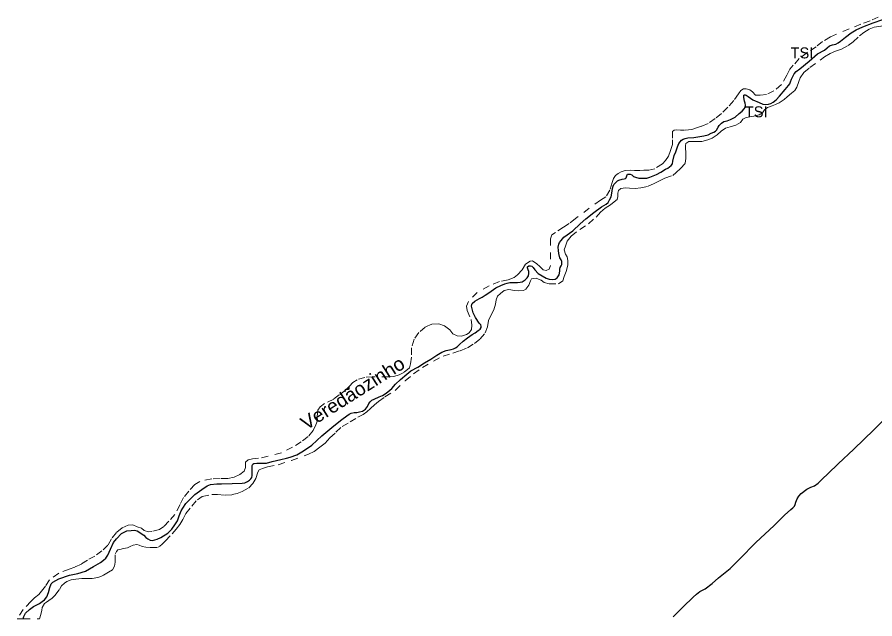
# Model space of a CAD drawing. Extents: x 391.8 to 446, y 8452 to 8507.5.
# Drawn here: x 414.05 to 426.58, y 8452.11 to 8460.91 of the extents above; entities that cross this region are included whole.
import ezdxf
from ezdxf.enums import TextEntityAlignment as Align

# ---------------------------------------------------------------- set-up
doc = ezdxf.new("R2010")
doc.units = 0
doc.header["$LTSCALE"] = 0.064
doc.linetypes.add('SHORT_DASHED', pattern=[2.7, 1.5, -1.2])
for name, color, linetype, lineweight in [('21', 7, 'SHORT_DASHED', 13), ('62', 7, 'SHORT_DASHED', 13), ('7', 7, 'Continuous', 25)]:
    doc.layers.add(name, color=color, linetype=linetype, lineweight=lineweight)
doc.layers.add('61', color=7, linetype='Continuous')

msp = doc.modelspace()

# ---------------------------------------------------------------- linework, layer by layer
at = {"layer": '21'}
for points in [[(426.6341, 8460.9076), (426.5128, 8460.8557), (426.3799, 8460.8037), (426.2065, 8460.7345), (425.935, 8460.6191), (425.8194, 8460.5498), (425.7269, 8460.4748), (425.5998, 8460.394), (425.4785, 8460.3017), (425.3918, 8460.2036), (425.3398, 8460.1459), (425.2994, 8460.0593), (425.2185, 8459.9208), (425.1087, 8459.8285), (424.9989, 8459.7766), (424.9065, 8459.765), (424.8406, 8459.768), (424.7943, 8459.8142), (424.7597, 8459.843), (424.7019, 8459.8603), (424.6672, 8459.8603), (424.6268, 8459.8373), (424.5921, 8459.7853), (424.5228, 8459.6872), (424.4361, 8459.5891), (424.3436, 8459.4968), (424.2512, 8459.4276), (424.1472, 8459.3525), (424.049, 8459.3121), (423.9796, 8459.2891), (423.9103, 8459.266), (423.8005, 8459.2544), (423.7427, 8459.2544), (423.6907, 8459.2602), (423.6503, 8459.2544), (423.6272, 8459.2371), (423.6272, 8459.116), (423.6252, 8459.0441), (423.5963, 8458.9576), (423.5674, 8458.8768), (423.527, 8458.8133), (423.4807, 8458.7614), (423.371, 8458.6921), (423.2843, 8458.669), (423.2092, 8458.669), (423.1514, 8458.6633), (423.0705, 8458.6633), (423.0069, 8458.669), (422.9376, 8458.6633), (422.8798, 8458.646), (422.8336, 8458.6229), (422.7932, 8458.594), (422.7643, 8458.5479), (422.7469, 8458.4902), (422.7123, 8458.3805), (422.6545, 8458.2824), (422.5736, 8458.2305), (422.2096, 8457.965), (422.1171, 8457.89), (422.0362, 8457.8381), (421.9191, 8457.7601), (421.8671, 8457.7255), (421.844, 8457.6678), (421.844, 8457.2754), (421.8267, 8457.2234), (421.7804, 8457.2061), (421.74, 8457.2119)], [(426.3591, 8460.6344), (426.4232, 8460.6833), (426.5023, 8460.7323), (426.5739, 8460.7586), (426.6756, 8460.7737), (426.7849, 8460.8), (426.9205, 8460.8489)], [(421.1665, 8456.9095), (421.2381, 8456.9284), (421.321, 8456.9133), (421.3738, 8456.9058), (421.4491, 8456.9095), (421.4868, 8456.9321), (421.5283, 8456.9886), (421.5509, 8457.0525), (421.5697, 8457.0826), (421.6338, 8457.0939), (421.6715, 8457.0789), (421.7091, 8457.0601), (421.7506, 8457.03), (421.8237, 8457.009), (421.9631, 8457.009), (422.0234, 8457.0541), (422.046, 8457.1181), (422.0724, 8457.1896), (422.0988, 8457.2837), (422.0988, 8457.3477), (422.0912, 8457.4041), (422.0649, 8457.4417), (422.0469, 8457.5074), (422.0658, 8457.5601), (422.0884, 8457.6316), (422.1487, 8457.7068), (422.273, 8457.8047), (422.4011, 8457.8837), (422.5104, 8457.9853), (422.5744, 8458.0568), (422.646, 8458.1133), (422.7214, 8458.1622), (422.7779, 8458.2073), (422.8202, 8458.2428), (422.8315, 8458.2842), (422.8315, 8458.3331), (422.839, 8458.3745), (422.8729, 8458.4008), (422.9408, 8458.4121), (423.0011, 8458.4083), (423.084, 8458.4046), (423.1668, 8458.4121), (423.2724, 8458.4347), (423.3477, 8458.4686), (423.4268, 8458.51), (423.5173, 8458.5513), (423.6303, 8458.5927), (423.6831, 8458.6341), (423.7434, 8458.6943), (423.815, 8458.7734), (423.8239, 8458.8389), (423.8201, 8458.933), (423.8164, 8458.9895), (423.8164, 8459.0309), (423.8239, 8459.061), (423.8654, 8459.0873), (423.9106, 8459.0911), (423.952, 8459.0911), (424.0538, 8459.0873), (424.1442, 8459.1137), (424.2082, 8459.14), (424.2798, 8459.1852), (424.3364, 8459.2416), (424.4004, 8459.2868), (424.472, 8459.3056), (424.5549, 8459.3282), (424.619, 8459.3658), (424.6566, 8459.4147), (424.6943, 8459.4335), (424.7509, 8459.4523), (424.8526, 8459.4674), (424.894, 8459.4787), (424.943, 8459.5088), (424.9732, 8459.554), (425.0146, 8459.5878), (425.0839, 8459.6125), (425.1329, 8459.6313), (425.1857, 8459.6539), (425.261, 8459.7028), (425.3025, 8459.7442), (425.3665, 8459.7969), (425.4155, 8459.8345), (425.4457, 8459.8834), (425.472, 8459.9662), (425.4947, 8460.0227), (425.5474, 8460.0979), (425.6341, 8460.1732), (425.7826, 8460.2769), (425.8504, 8460.3296), (425.9295, 8460.3785), (426.0087, 8460.4086), (426.0953, 8460.4387), (426.1933, 8460.4914), (426.2649, 8460.5479), (426.3591, 8460.6344)], [(421.48, 8457.2985), (421.4337, 8457.2119), (421.3644, 8457.1427), (421.3124, 8457.1023), (421.2257, 8457.0676), (421.0986, 8457.0446), (420.9484, 8456.9811), (420.7751, 8456.883), (420.6459, 8456.7524), (420.6171, 8456.6832), (420.6286, 8456.6197), (420.6864, 8456.487), (420.6979, 8456.4062), (420.6922, 8456.3427), (420.6575, 8456.2908), (420.6171, 8456.2677), (420.5477, 8456.2446), (420.4842, 8456.2504), (420.4206, 8456.2792), (420.3744, 8456.337), (420.2993, 8456.3947), (420.2126, 8456.4235), (420.1144, 8456.4177), (420.0161, 8456.3773), (419.9237, 8456.2966), (419.8544, 8456.1985), (419.8139, 8456.0715), (419.8139, 8455.9388), (419.8024, 8455.8407), (419.785, 8455.783), (419.7019, 8455.7107), (419.6326, 8455.6761), (419.5575, 8455.653), (419.4824, 8455.6473), (419.2512, 8455.6473), (419.1357, 8455.6415), (419.0201, 8455.6069), (418.9566, 8455.5665), (418.9103, 8455.5145), (418.8468, 8455.4511), (418.7601, 8455.3876), (418.6792, 8455.3241), (418.5463, 8455.2606), (418.4828, 8455.2087), (418.4481, 8455.1625), (418.4423, 8455.1164), (418.4365, 8455.0644), (418.4423, 8455.0125), (418.4192, 8454.949), (418.3788, 8454.8625), (418.3036, 8454.7759), (418.2054, 8454.7009), (418.0783, 8454.6201), (417.9165, 8454.5393), (417.7201, 8454.4874), (417.5814, 8454.4585), (417.4947, 8454.4528), (417.4312, 8454.4355), (417.3907, 8454.4008), (417.3907, 8454.3258), (417.3702, 8454.2713), (417.3067, 8454.2193), (417.2258, 8454.1847), (417.1334, 8454.1616), (417.0178, 8454.1616), (416.8965, 8454.1559), (416.7231, 8454.1212), (416.648, 8454.0751), (416.5613, 8453.977), (416.4862, 8453.8847), (416.4342, 8453.7808), (416.3591, 8453.6365), (416.2724, 8453.5384), (416.1973, 8453.4634), (416.1338, 8453.4173), (416.024, 8453.3884), (415.972, 8453.3826), (415.9119, 8453.4033), (415.8714, 8453.438), (415.8078, 8453.4553), (415.7443, 8453.4841), (415.675, 8453.4784), (415.5883, 8453.4437), (415.5074, 8453.3745), (415.4323, 8453.2822), (415.3803, 8453.1898), (415.2936, 8453.1033), (415.1896, 8453.0283), (415.0798, 8452.9706), (414.9931, 8452.9129), (414.8949, 8452.8667), (414.814, 8452.8378), (414.6638, 8452.7801), (414.5251, 8452.682), (414.4673, 8452.5897)], [(421.74, 8457.2119), (421.6938, 8457.2581), (421.6418, 8457.3042), (421.6186, 8457.3215), (421.584, 8457.3446), (421.5493, 8457.3389), (421.48, 8457.2985)], [(420.9744, 8456.5445), (421.0158, 8456.6273), (421.0422, 8456.7139), (421.0535, 8456.7741), (421.0723, 8456.8267), (421.1138, 8456.8681), (421.1665, 8456.9095)], [(414.3804, 8452.1122), (414.4018, 8452.1725), (414.4131, 8452.2402), (414.4207, 8452.2778), (414.4546, 8452.3343), (414.4847, 8452.3569), (414.5186, 8452.3795), (414.5638, 8452.4133), (414.6053, 8452.4547), (414.6731, 8452.5413), (414.7033, 8452.594), (414.7447, 8452.6316), (414.7786, 8452.6579), (414.8427, 8452.6805), (414.9105, 8452.6918), (414.9972, 8452.6993), (415.0688, 8452.6993), (415.1479, 8452.7031), (415.2308, 8452.7144), (415.276, 8452.7294), (415.3137, 8452.7482), (415.3891, 8452.7934), (415.4456, 8452.8273), (415.4757, 8452.88), (415.487, 8452.9402), (415.487, 8453.0568), (415.5036, 8453.0958), (415.5262, 8453.1221), (415.5564, 8453.1259), (415.6091, 8453.1409), (415.6656, 8453.1485), (415.7071, 8453.171), (415.7485, 8453.1899), (415.8013, 8453.1974), (415.839, 8453.1861), (415.8804, 8453.1673), (415.9332, 8453.1597), (415.9972, 8453.156), (416.1027, 8453.156), (416.1404, 8453.1748), (416.1743, 8453.2049), (416.2195, 8453.2538), (416.3178, 8453.3565), (416.3781, 8453.4242), (416.4308, 8453.4919), (416.476, 8453.5634), (416.5175, 8453.65), (416.6041, 8453.7591), (416.687, 8453.8532), (416.7549, 8453.8984), (416.8963, 8453.9267), (416.9829, 8453.9267), (417.0922, 8453.9192), (417.1977, 8453.9267), (417.2693, 8453.9417), (417.3409, 8453.9718), (417.4389, 8454.0283), (417.4954, 8454.0885), (417.5406, 8454.1638), (417.5708, 8454.2541), (417.5896, 8454.2879), (417.6386, 8454.3105), (417.7102, 8454.3331), (417.8684, 8454.3632), (418.0606, 8454.4272), (418.3093, 8454.5175), (418.3939, 8454.5601), (418.4768, 8454.6203), (418.556, 8454.6805), (418.6238, 8454.7596), (418.7105, 8454.8386), (418.8009, 8454.9214), (418.9177, 8454.9891), (419.0307, 8455.0606), (419.1073, 8455.1001), (419.1601, 8455.1377), (419.2166, 8455.1866), (419.2731, 8455.2393), (419.3334, 8455.2882), (419.4276, 8455.356), (419.5784, 8455.45), (419.7215, 8455.593), (419.8459, 8455.6946), (419.974, 8455.785), (420.136, 8455.879), (420.2755, 8455.9505), (420.4203, 8455.9973), (420.5258, 8456.0312), (420.6313, 8456.0726), (420.7368, 8456.1365), (420.8159, 8456.2043), (420.8913, 8456.2908), (420.9252, 8456.3811), (420.9403, 8456.4752), (420.9744, 8456.5445)], [(414.4673, 8452.5897), (414.4096, 8452.5147), (414.3691, 8452.4685), (414.3056, 8452.4166), (414.2536, 8452.3647), (414.1438, 8452.2493), (414.0545, 8452.1111)]]:
    msp.add_lwpolyline(points, dxfattribs=at)
at = {"layer": '62'}
msp.add_lwpolyline([(414.0545, 8452.1111), (414.1446, 8452.1114), (414.3804, 8452.1122)], dxfattribs=at)
at = {"layer": '7'}
for points in [[(422.9718, 8458.6099), (422.9906, 8458.6136), (423.0094, 8458.6118), (423.0319, 8458.6005), (423.0582, 8458.5799), (423.0883, 8458.5667), (423.1352, 8458.5536), (423.1784, 8458.5517), (423.2254, 8458.5517), (423.2536, 8458.5555), (423.2968, 8458.5705), (423.3944, 8458.608), (423.4583, 8458.6399), (423.5278, 8458.683), (423.5597, 8458.6999), (423.5842, 8458.7187), (423.6067, 8458.7393), (423.6255, 8458.7637), (423.633, 8458.8012), (423.6537, 8458.8838), (423.6743, 8458.94), (423.7012, 8459.0105), (423.72, 8459.0593), (423.7388, 8459.0837), (423.7613, 8459.108), (423.7839, 8459.123), (423.8139, 8459.1343), (423.8496, 8459.1456), (423.9416, 8459.1493), (424.0863, 8459.1737), (424.1464, 8459.1887), (424.1934, 8459.2112), (424.2328, 8459.2262), (424.2572, 8459.2412), (424.2722, 8459.2562), (424.2929, 8459.2975), (424.3117, 8459.3256), (424.3455, 8459.3594), (424.3769, 8459.381), (424.4276, 8459.3922), (424.4765, 8459.411), (424.5422, 8459.4448), (424.6023, 8459.4973), (424.6474, 8459.5348), (424.6756, 8459.5648), (424.6868, 8459.5873), (424.6925, 8459.6211), (424.6906, 8459.6511), (424.6812, 8459.6774), (424.6737, 8459.7036), (424.6699, 8459.7393), (424.6699, 8459.7571), (424.6718, 8459.7665), (424.6793, 8459.7702), (424.6906, 8459.7702), (424.7056, 8459.7683), (424.7319, 8459.7477), (424.8014, 8459.6989), (424.8916, 8459.6576), (424.9479, 8459.637), (424.9911, 8459.6314), (425.0287, 8459.637), (425.0644, 8459.6464), (425.0982, 8459.6633), (425.1414, 8459.697), (425.1903, 8459.7514), (425.2748, 8459.8509), (425.3236, 8459.909), (425.3417, 8459.9324), (425.3511, 8459.9605), (425.3642, 8459.9999), (425.383, 8460.0393), (425.4056, 8460.0787), (425.4337, 8460.1125), (425.4863, 8460.1537), (425.6235, 8460.2663), (425.7437, 8460.3695), (425.8457, 8460.4266), (425.887, 8460.4604), (425.9227, 8460.4885), (425.964, 8460.5016), (426.0129, 8460.5148), (426.0486, 8460.5316), (426.0805, 8460.5542), (426.1556, 8460.6142), (426.2364, 8460.6761), (426.3083, 8460.7205), (426.4098, 8460.7674), (426.56, 8460.8255), (426.699, 8460.8724)], [(422.8923, 8458.5394), (422.9205, 8458.5432), (422.9393, 8458.5469), (422.9505, 8458.5582), (422.9599, 8458.5863), (422.9643, 8458.6005), (422.9718, 8458.6099)], [(420.0053, 8455.8542), (420.0992, 8455.9086), (420.1837, 8455.9667), (420.2589, 8456.008), (420.3209, 8456.0343), (420.3922, 8456.0474), (420.429, 8456.0582), (420.4572, 8456.0713), (420.4816, 8456.0882), (420.5173, 8456.1201), (420.5699, 8456.1726), (420.6337, 8456.2176), (420.6995, 8456.2664), (420.7464, 8456.2945), (420.7896, 8456.3246), (420.8159, 8456.3471), (420.831, 8456.3696), (420.8328, 8456.3883), (420.8291, 8456.4071), (420.8047, 8456.4352), (420.7502, 8456.5178), (420.7145, 8456.5834), (420.6957, 8456.6622), (420.6919, 8456.6821), (420.6956, 8456.7083), (420.7013, 8456.7196), (420.7407, 8456.7534), (420.8102, 8456.7928), (420.8497, 8456.8153), (420.891, 8456.8415), (420.9323, 8456.8697), (420.9793, 8456.9034), (421.045, 8456.9503), (421.122, 8456.986), (421.1803, 8457.0085), (421.2103, 8457.0198), (421.2516, 8457.0273), (421.3118, 8457.0291), (421.3652, 8457.0263), (421.4046, 8457.0319), (421.4309, 8457.0394), (421.4741, 8457.0675), (421.5061, 8457.0957), (421.5248, 8457.1276), (421.5286, 8457.1595), (421.5286, 8457.1876), (421.5173, 8457.2139), (421.5079, 8457.2439), (421.5117, 8457.2589), (421.5267, 8457.2701), (421.553, 8457.272), (421.5737, 8457.2664), (421.5906, 8457.2495), (421.615, 8457.2139), (421.6657, 8457.1595), (421.7221, 8457.1238), (421.7803, 8457.0919), (421.8273, 8457.075), (421.8742, 8457.0713), (421.9137, 8457.0788), (421.9418, 8457.0957), (421.97, 8457.1426), (421.9794, 8457.1932), (421.9794, 8457.2251), (421.9869, 8457.2476), (422.002, 8457.272), (422.0132, 8457.2927), (422.0132, 8457.3339), (422.0076, 8457.3489), (422.002, 8457.3621), (421.9813, 8457.3902), (421.969, 8457.4512), (421.9615, 8457.4944), (421.9596, 8457.5469), (421.9653, 8457.5863), (421.9784, 8457.6126), (422.001, 8457.6445), (422.0423, 8457.6895), (422.17, 8457.7852), (422.2772, 8457.8837), (422.3618, 8457.9587), (422.4801, 8458.0525), (422.5918, 8458.1342), (422.6575, 8458.1755), (422.6857, 8458.1999), (422.7082, 8458.2355), (422.7327, 8458.2824), (422.7402, 8458.335), (422.7514, 8458.4044), (422.7608, 8458.4381), (422.7721, 8458.4606), (422.789, 8458.4813), (422.8247, 8458.515), (422.8435, 8458.5263), (422.8923, 8458.5394)], [(419.5258, 8455.4797), (419.5803, 8455.5416), (419.6535, 8455.611), (419.7474, 8455.6879), (419.8075, 8455.7386), (419.9057, 8455.7923), (420.0053, 8455.8542)], [(414.1446, 8452.1114), (414.1521, 8452.1466), (414.1769, 8452.1926), (414.2335, 8452.2492), (414.2937, 8452.2916), (414.3787, 8452.334), (414.4212, 8452.3658), (414.4531, 8452.3906), (414.4885, 8452.433), (414.5133, 8452.4967), (414.531, 8452.5709), (414.5522, 8452.624), (414.577, 8452.6452), (414.6655, 8452.6982), (414.8178, 8452.7513), (414.9417, 8452.7725), (415.055, 8452.8079), (415.1691, 8452.8764), (415.2718, 8452.9365), (415.3143, 8452.9683), (415.3497, 8453.0002), (415.378, 8453.0426), (415.4205, 8453.131), (415.463, 8453.2265), (415.5055, 8453.2831), (415.5798, 8453.3573), (415.6577, 8453.3962), (415.7179, 8453.4033), (415.771, 8453.4068), (415.8064, 8453.3997), (415.9056, 8453.3361), (415.9339, 8453.3007), (415.9622, 8453.2795), (415.9976, 8453.2618), (416.031, 8453.2574), (416.0648, 8453.2649), (416.0986, 8453.2743), (416.1531, 8453.3005), (416.2545, 8453.3624), (416.3127, 8453.4243), (416.3559, 8453.4844), (416.3991, 8453.5444), (416.4217, 8453.6194), (416.448, 8453.6888), (416.4724, 8453.7301), (416.5175, 8453.7958), (416.5851, 8453.8671), (416.6496, 8453.9279), (416.7511, 8454.003), (416.83, 8454.0536), (416.8788, 8454.0761), (416.969, 8454.0874), (417.0403, 8454.0874), (417.1944, 8454.0892), (417.339, 8454.093), (417.3796, 8454.101), (417.4209, 8454.1179), (417.4491, 8454.1366), (417.4698, 8454.1592), (417.4811, 8454.176), (417.4886, 8454.2061), (417.4886, 8454.3534), (417.498, 8454.3703), (417.513, 8454.3816), (417.5581, 8454.3872), (417.6445, 8454.3872), (417.6971, 8454.3891), (417.7798, 8454.4097), (417.9075, 8454.4416), (417.9901, 8454.4604), (418.0427, 8454.4754), (418.1385, 8454.5091), (418.2391, 8454.5696), (418.3574, 8454.6522), (418.5058, 8454.7872), (418.6786, 8454.9335), (418.7997, 8455.0234), (418.8692, 8455.0815), (418.9049, 8455.1022), (418.9331, 8455.1172), (418.9763, 8455.1265), (419.0157, 8455.1284), (419.0571, 8455.1359), (419.1003, 8455.1491), (419.1435, 8455.1753), (419.1735, 8455.2166), (419.1923, 8455.2597), (419.2111, 8455.2841), (419.2355, 8455.3066), (419.2712, 8455.3235), (419.3445, 8455.3573), (419.3914, 8455.3779), (419.429, 8455.4004), (419.4684, 8455.4286), (419.5258, 8455.4797)], [(423.6397, 8452.1415), (423.7814, 8452.2855), (423.9273, 8452.428), (423.9759, 8452.4734), (424.0278, 8452.5122), (424.1056, 8452.5511), (424.2094, 8452.6256), (424.3002, 8452.713), (424.4721, 8452.849), (424.6082, 8452.9818), (424.8459, 8453.226), (425.1118, 8453.4753), (425.2648, 8453.6269), (425.3556, 8453.7111), (425.3848, 8453.7338), (425.4075, 8453.7564), (425.4205, 8453.7824), (425.4302, 8453.818), (425.4464, 8453.8665), (425.4723, 8453.9054), (425.508, 8453.9443), (425.5891, 8454.009), (425.6507, 8454.0349), (425.7026, 8454.0576), (425.7544, 8454.0965), (425.8161, 8454.1515), (425.9036, 8454.2357), (426.0463, 8454.375), (426.2746, 8454.5937), (426.5697, 8454.8754), (426.748, 8455.0535)]]:
    msp.add_lwpolyline(points, dxfattribs=at)

# ---------------------------------------------------------------- texts
at = {"layer": '61'}
for p in [(425.5184, 8460.3048), (424.8506, 8459.444)]:
    msp.add_text('TSI', height=0.16, dxfattribs=at).set_placement(p, align=Align.CENTER)
at = {"layer": '61', "width": 1.05}
msp.add_text('Veredãozinho', height=0.2, rotation=32.428, dxfattribs=at).set_placement((419.0081, 8455.3269), align=Align.CENTER)

doc.saveas('drawing.dxf')
